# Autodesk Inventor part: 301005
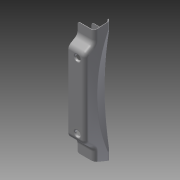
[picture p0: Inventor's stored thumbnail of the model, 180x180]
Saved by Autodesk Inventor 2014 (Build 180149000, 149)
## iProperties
Created: 2007-11
Part Number: 301005
Document SubType Name: Modeling
Designer: TH
Density: 7.85 g/cm^3
Mass: 285.829 g
Surface Area: 737.341 cm^2
Volume: 36.4113 cm^3
Material: Steel
Description: TOP PLATE MOUNT
Appearance: Steel
Component Category: Back Component
Author: TH
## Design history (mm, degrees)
sketch "Sketch1"
  geometry: L1 (0, 0)-(11.288, 56.351); L2 (-37.872, 56.329)-(11.288, 56.351); L3 (-42.63, 0)-(0, 0); L4 (-37.872, 56.329)-(-37.872, 27.892); L5 (-42.63, 0)-(-37.872, 27.892); L6 (0, 67.621)-(0, -11.27) reference
  constraints: 11 end point, 1 perpendicular
  dimensions: "d0" = 42.63046 distance of L3.start L1.start; "d1" = 80.318 deg angle of L5 L3; "d2" = 78.6722 deg angle of L1 L3; "d4" = 56.35095 distance from line of L3 L1.end; "d5" = 56.32872 distance from line of L3 L2.start; "d6" = 37.87181 distance from line of L1.start L4; "d8" = 37.87181 horizontal distance of L1.start L2.start
extrude "Extrusion1" new body sketch "Sketch1" stored distance "d9" = 315; taper "d10" = 0 deg
sketch "Sketch2"
  geometry: L1 (56.346, -157.5)-(0, -157.5) reference; L2 (0, -157.5)-(0, 157.5) reference; L3 (0, 157.5)-(56.346, 157.5) reference; L4 (56.346, 157.5)-(56.346, -157.5) reference; L5 (56.346, 157.5)-(20.439, 147.009); L6 (20.439, 147.009)-(20.439, 118.184); L7 (0, 100.195)-(20.439, 118.184); L8 (0, 100.195)-(0, 157.5); L9 (0, 157.5)-(56.346, 157.5); 1 further point
  constraints: 10 end point, 2 parallel, 1 collinear, 1 point on line
  dimensions: "d11" = 100.19492 distance of L7.start point (0, 0); "d12" = 118.1843 vertical distance of point (0, 0) L6.end; "d13" = 20.43943 distance between parallel lines of L8 L6; "d14" = 147.00907 vertical distance of point (0, 0) L5.end
extrude "Extrusion2" cut sketch "Sketch2" stored distance "d15" = 326; taper "d16" = 0 deg
mirror "Mirror1"
workplane "Work Plane1"
sketch "Sketch3"
  geometry: L1 (-4.486, 27.612)-(2.13, 4.618) reference; L2 (-764.894, -222.794)-(-764.894, 577.206); L3 (-764.894, -222.794)-(35.106, -222.794); A1 r 800 centre (-764.894, -222.794) between (35.106, -222.794) and (-764.894, 577.206); 1 further point
  constraints: 6 end point, 2 point on circle, 1 centre point, 1 perpendicular, 1 tangent, 1 vertical, 3 other
  dimensions: "d17" = 1600 diameter of A1; "d20" = 767.02398 horizontal distance of L1.end L2.start
revolve "Revolution1" sketch "Sketch3" stored, may be unused: angle "d19" = 90 deg
fillet "Fillet1" dims "d21" = 16
fillet "Fillet2" dims "d22" = 10
fillet "Fillet3" dims "d23" = 6
fillet "Fillet4" dims "d24" = 3
shell "Shell1" dims "d25" = 1
sketch "Sketch4"
  geometry: L1 (0, 0)-(0, 2.405) reference; L2 (46.124, 0)-(0, 0) reference; L3 (41.836, 2.424)-(0, 2.405) reference; A1 r 5 centre (41.838, -2.576) between (46.124, 0) and (41.836, 2.424) reference; 1 further point
extrude "Extrusion3" cut sketch "Sketch4" stored distance "d26" = 326; taper "d27" = 0 deg
sketch "Sketch5"
  geometry: L1 (46.124, 2.405)-(46.124, 0) reference; L2 (46.124, 2.405)-(4.288, 2.424) reference; L3 (46.124, 0)-(0, 0) reference; A1 r 5 centre (4.286, -2.576) between (4.288, 2.424) and (0, 0) reference; 1 further point
extrude "Extrusion4" cut sketch "Sketch5" stored distance "d28" = 326; taper "d29" = 0 deg
fillet "Fillet5" dims "d30" = 5
sketch "Sketch6"
  geometry: L1 (41.836, 314.995)-(37.872, 314.995) reference; L2 (37.872, 314.995)-(0, 314.99) reference; L3 (0, 0)-(0, 314.99) reference; L4 (0, 0)-(37.872, -0.005) reference; L5 (37.872, -0.005)-(41.836, -0.005) reference; L6 (41.836, 33.729)-(41.836, -0.005) reference; L7 (39.854, -0.005)-(39.854, 24.495); L8 (34.854, 29.495)-(0, 29.495); L9 (39.854, 314.995)-(39.854, 290.495); L10 (34.854, 285.495)-(0, 285.495); L11 (-5, 0.001)-(0, 0.001); L12 (0, 0.001)-(0, 29.495); L13 (0, 29.495)-(-5, 29.495); L14 (-5, 29.495)-(-5, 0.001); L15 (-5, 314.99)-(0, 314.99); L16 (0, 314.99)-(0, 285.495); L17 (0, 285.495)-(-5, 285.495); L18 (-5, 285.495)-(-5, 314.99); L19 (0, 118.495)-(10.5, 118.495); L20 (10.5, 118.495)-(10.5, 196.495); L21 (10.5, 196.495)-(0, 196.495); L22 (0, 196.495)-(0, 118.495); L23 (10.5, 118.495)-(0, 105.982); L24 (10.5, 196.495)-(0, 209.008); L25 (0, 105.982)-(0, 118.495); L26 (0, 196.495)-(0, 209.008); L27 (0, 105.982)-(-3, 102.406); L28 (-3, 102.406)-(-3, 212.584); L29 (0, 209.008)-(-3, 212.584); A1 r 5 centre (34.854, 24.495) between (39.854, 24.495) and (34.854, 29.495); A2 r 5 centre (34.854, 290.495) between (34.854, 285.495) and (39.854, 290.495); 2 further points
  constraints: 46 end point, 8 parallel, 6 perpendicular, 5 point on line, 4 collinear, 4 midpoint, 4 point on circle, 4 tangent, 3 horizontal, 2 centre point, 1 equal radius
  dimensions: "d31" = 128 distance from line of point (37.846, 157.495) L10; "d32" = 128 distance from line of point (37.846, 157.495) L8 (= d31); "d33" = 5 radius of A1; "d36" = 5 distance between parallel lines of L14 L12; "d37" = 5 distance between parallel lines of L18 L16; "d38" = 10.5 distance of L19.start L19.end; "d39" = 50 deg angle of L23 L19; "d40" = 50 deg angle of L21 L24 (= d39); "d41" = 78 distance of L19.end L20.end; "d42" = 3 distance between parallel lines of L28 L3
extrude "Extrusion5" cut sketch "Sketch6" distance "d34" = 1; taper "d35" = 0 deg
fillet "Fillet6" dims "d43" = 10
fillet "Fillet7" dims "d44" = 5
sketch "Sketch7"
  geometry: C1 r 6.9 at (23.16, 177.963); C2 r 6.9 at (23.16, 7.963); 1 further point
  constraints: 2 centre point
  dimensions: "d45" = 85 vertical distance of C1.centre point (42.63, 92.963); "d46" = 85 vertical distance of point (42.63, 92.963) C2.centre (= d45); "d47" = 19.47007 horizontal distance of C1.centre point (42.63, 92.963); "d48" = 19.47007 horizontal distance of point (42.63, 92.963) C2.centre (= d47); "d49" = 13.8 diameter of C2 (= d50); "d50" = 13.8 diameter of C1
extrude "Extrusion6" cut sketch "Sketch7" stored distance "d51" = 1; taper "d52" = 0 deg
sketch "Sketch8"
  geometry: C1 r 6.9 at (22.99, -7.963) reference; C2 r 6.9 at (22.99, -177.963) reference; C3 r 7.9 at (22.99, -177.963); C4 r 7.9 at (22.99, -7.963); 1 further point
  constraints: 2 centre point, 2 coincident
  dimensions: "d53" = 15.8 diameter of C4; "d54" = 15.8 diameter of C3 (= d53)
extrude "Extrusion7" join sketch "Sketch8" distance "d55" = 3.5; taper "d56" = 0 deg
sketch "Sketch9"
  geometry: C1 r 7.9 at (-784.031, -85); C2 r 7.9 at (-784.031, 85); 3 further points; 2 other entities
  constraints: 2 centre point, 2 coincident, 2 other
  dimensions: "d59" = 15.8 diameter of C1; "d60" = 15.8 diameter of C2 (= d59)
extrude "Extrusion8" join sketch "Sketch9" distance "d61" = 3.5; taper "d62" = 0 deg
fillet "Fillet8" dims "d57" = 2
fillet "Fillet9" dims "d58" = 3
sketch "Sketch10"
  geometry: L1 (-762.579, -133)-(-762.579, -152.292) reference; L2 (-788.586, -53.5)-(-788.586, 53.5); L3 (-828.745, 0)-(-757.594, 0) reference; 4 further points
  constraints: 4 end point, 2 coincident, 1 horizontal, 1 midpoint, 1 parallel, 1 point on line, 2 other
  dimensions: "d63" = 107 distance of L2.start L2.end; "d64" = 24 distance from line of point (-764.586, 0) L2
hole "Hole1" sketch "Sketch10" at (-788.586, -53.5), (-788.586, 53.5) diameter "d65" = 8.5; stored, may be unused: countersink angle "d69" = 90 deg, drill point angle "d71" = 118 deg; dims "d66" = 6, "d67" = 4, "d68" = 2, "d70" = 2
body "Solid1"
node "Project Cut Edges1"
